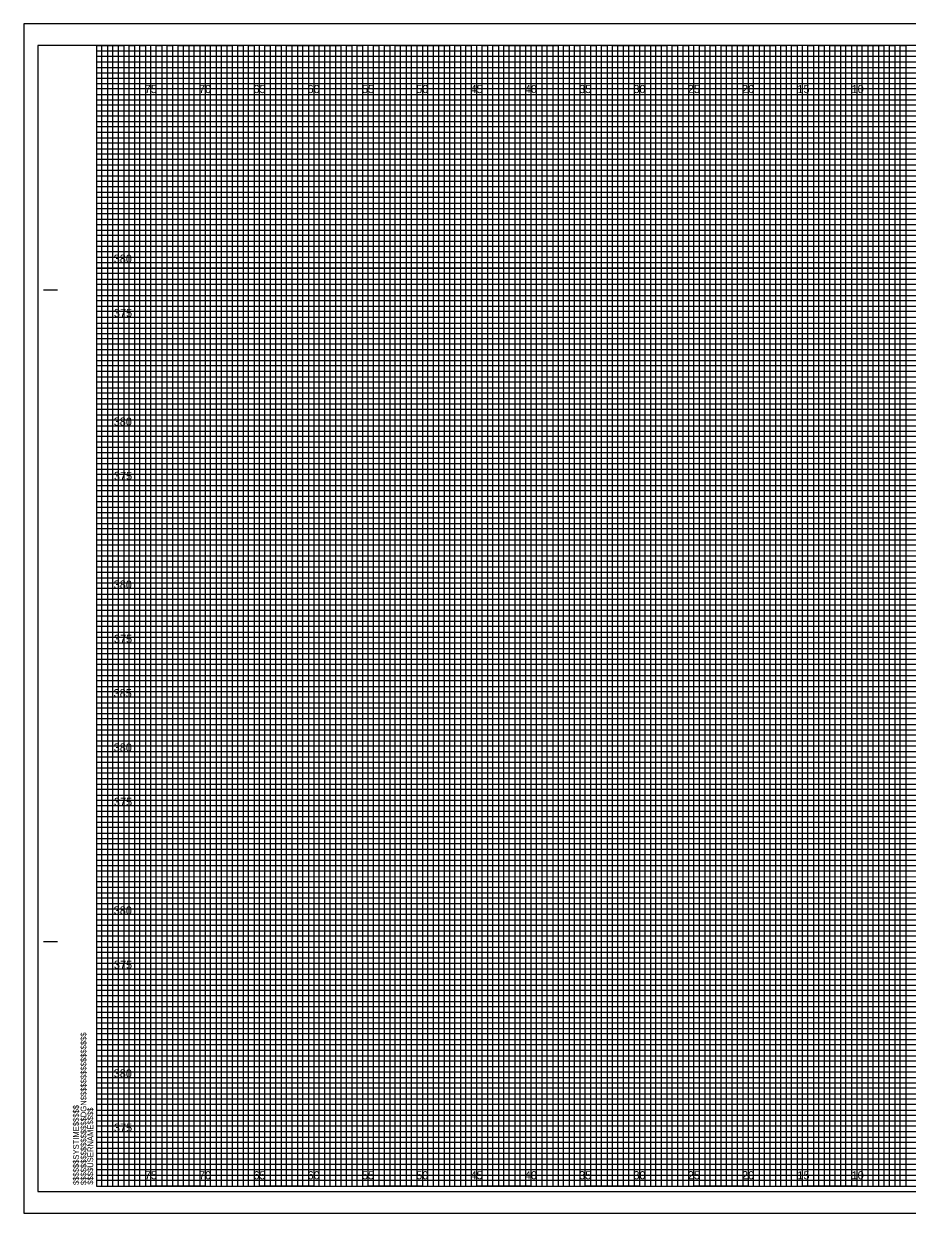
# Model space of a CAD drawing. Extents: x -7 to 162, y -2 to 217.
# Drawn here: x -6.7 to 74.6, y -2.5 to 107 of the extents above; entities that cross this region are included whole.
import ezdxf

# ---------------------------------------------------------------- set-up
doc = ezdxf.new("R2010")
doc.units = 0
for name, color, linetype in [('Exist Cross Section Cell', 7, 'Continuous'), ('Prop CMT Pvmt Course 1', 7, 'Continuous'), ('Prop CMT Pvmt Course 3', 7, 'Continuous'), ('Prop CMT Shld Paved Course 1', 7, 'Continuous'), ('Prop CMT Shld Paved Course 2', 7, 'Continuous'), ('Prop CMT Shld Paved Course 3', 7, 'Continuous'), ('Prop CMT Slope Grass', 7, 'Continuous'), ('Prop CMT Subgrade Earthwork', 7, 'Continuous'), ('Scratch_Level_3', 7, 'Continuous')]:
    doc.layers.add(name, color=color, linetype=linetype)

msp = doc.modelspace()

# ---------------------------------------------------------------- linework, layer by layer
at = {"layer": 'Prop CMT Pvmt Course 3'}
msp.add_lwpolyline([(-6.7, -2.5), (161.65, -2.5), (161.65, 107), (-6.7, 107)], close=True, dxfattribs=at)
at = {"layer": 'Prop CMT Shld Paved Course 1'}
for p, q in [((0, 104.5), (110.95, 104.5)), ((110.95, 103.99), (0, 103.99)), ((0, 103.99), (0, 103.5)), ((0, 103.5), (110.95, 103.5)), ((110.95, 102.95), (0, 102.95)), ((0, 102.95), (0, 102)), ((0, 102), (160, 102))]:
    msp.add_line(p, q, dxfattribs=at)
for points in [[(0, 101.5), (135, 101.5), (160, 101.5)], [(160, 101), (0, 101)], [(0, 100.5), (160, 100.5)], [(160, 99.5), (0, 99.5)], [(0, 99), (160, 99)], [(160, 98.5), (0, 98.49)], [(0, 98), (160, 98)], [(160, 97), (0, 97)], [(0, 96.5), (160, 96.5), (160, 96), (0, 96)], [(0, 95.5), (160, 95.5), (160, 94.5), (0, 94.5)], [(0, 94), (160, 94), (160, 93.5), (0, 93.5)], [(0, 93), (160, 93), (160, 92), (0, 92)], [(0, 91.5), (160, 91.5), (160, 91), (0, 91)], [(0, 90.5), (160, 90.5), (160, 89.5), (0, 89.5)], [(0, 89), (160, 89), (160, 88.5), (0, 88.5)], [(0, 88), (160, 88), (160, 86.97), (160, 86.5), (160, 86), (0, 86)], [(0, 87), (160, 87), (160, 86.5), (0, 86.5)], [(0, 85.5), (160, 85.5), (160, 84.5), (0, 84.51)], [(0, 84.51), (160, 84.5), (160, 84), (0, 84)], [(0, 83.5), (160, 83.5), (160, 83), (0, 83)], [(0, 82), (160, 82), (160, 81.5), (0, 81.5)], [(0, 81), (160, 81), (160, 80.5), (0, 80.5)], [(-0.04, 79.44), (160, 79.44), (160, 78.94), (-0.04, 78.94)], [(0, 78.5), (160, 78.5), (160, 78), (0, 78)], [(0, 77), (160, 77), (160, 76.5), (0, 76.5)], [(0, 76), (160, 76), (160, 75.5), (0, 75.5)], [(0, 74.5), (160, 74.5), (160, 74), (0, 74)], [(0, 73.5), (160, 73.5), (160, 73), (0, 73)], [(0, 72), (160, 72), (160, 71.5), (0, 71.5)], [(0, 71), (160, 71), (160, 70.5), (0, 70.5)], [(0, 69.5), (160, 69.5), (159.99, 68.99), (0, 69)], [(0, 68.5), (160, 68.5), (160, 68), (0, 68)], [(0, 67), (160, 67), (160, 66.5), (0, 66.5)], [(0, 66), (160, 66), (160, 65.5), (0, 65.5)], [(0, 64.5), (160, 64.5), (160, 64), (0, 64)], [(0, 63.5), (160, 63.5), (160, 63), (0, 63)], [(0, 62), (160, 62), (160, 61.5), (0, 61.5)], [(0, 61), (160, 61), (160, 60.5), (0, 60.5)], [(0, 59.5), (160, 59.5), (160, 59), (0, 59)], [(0, 58.5), (160.03, 58.45), (160, 58), (0, 58)], [(0, 57), (160, 57), (160, 56.5), (0, 56.5)], [(0, 56), (160, 56), (160, 55.5), (0, 55.5)], [(0, 54.5), (160, 54.5), (160, 54), (0, 54)], [(0, 53.5), (160, 53.5), (160, 53), (0, 53)], [(0, 52), (160, 52), (160, 51.5), (0, 51.5)], [(0, 51), (160, 51), (160, 50.5), (0, 50.5)], [(0, 49.5), (160, 49.5), (160, 49), (0, 49)], [(0, 48.5), (160, 48.5), (160, 48), (0, 48)], [(0, 47), (160, 47), (160, 46.5), (0, 46.5)], [(0, 46), (160, 46), (160, 45.5), (0, 45.5)], [(0, 44.5), (160, 44.5), (160, 44), (0, 44)], [(0, 43.5), (160, 43.5), (160, 43), (0, 43)], [(0, 42), (160, 42), (160, 41.5), (0, 41.5)], [(0, 41), (160, 41), (160, 40.5), (0, 40.5)], [(0, 39.5), (160, 39.5), (159.99, 38.99), (0, 39)], [(0, 38.5), (160, 38.5), (160, 38), (0, 38)], [(0, 37), (160, 37), (160, 36.5), (0, 36.5)], [(0, 36), (160, 36), (160, 35.5), (0, 35.5)], [(0, 34.5), (160, 34.5), (160, 34), (0, 34)], [(0, 33.5), (160, 33.5), (160, 33), (0, 33)], [(0, 32), (160, 32), (160, 31.5), (0, 31.5)], [(0, 31), (160, 31), (160, 30.5), (0, 30.5)], [(0, 29.5), (160, 29.5), (160, 29), (0, 29)], [(0, 28.5), (160.03, 28.46), (160, 28), (0, 28)], [(0, 27), (160, 27), (160, 26.5), (0, 26.5)], [(0, 26), (160, 26), (160, 25.5), (0, 25.5)], [(0, 24.5), (160, 24.5), (160, 24), (0, 24)], [(0, 23.5), (160, 23.5), (160, 23), (0, 23)], [(0, 22), (160, 22), (160, 21.5), (0, 21.5)], [(0, 21), (160, 21), (160, 20.5), (0, 20.5)], [(0, 19.5), (160, 19.5), (160, 19), (0, 19)], [(0, 18.5), (160, 18.5), (160, 18), (0, 18)], [(0, 17), (160, 17), (160, 16.5), (0, 16.5)], [(0, 16), (160, 16), (160, 15.5), (0, 15.5)], [(0, 14.5), (160, 14.5), (160, 14), (0, 14)], [(0, 13.5), (160, 13.5), (160, 13), (0, 13)], [(0, 12), (160, 12), (160, 11.5), (0, 11.5)], [(0, 11), (160, 11), (160, 10.5), (0, 10.5)], [(0, 9.5), (160, 9.5), (160, 9), (0, 9)], [(0, 8.5), (160, 8.5), (160, 8), (0, 8)], [(0, 7), (160, 7), (160, 6.5), (0, 6.5)], [(0, 6), (160, 6), (160, 5.5), (0, 5.5)], [(0, 4.5), (160, 4.5), (160, 4), (0, 4)], [(0, 3.5), (160, 3.5), (160, 3), (0, 3)], [(0, 2), (160, 2), (160, 1.5), (0, 1.5)], [(0, 1), (160, 1), (160, 0.5), (0, 0.5)]]:
    msp.add_lwpolyline(points, dxfattribs=at)
at = {"layer": 'Prop CMT Shld Paved Course 2'}
for p, q in [((-4.9, 82.5), (-3.65, 82.5)), ((-4.85, 82.5), (-3.6, 82.5)), ((-4.9, 22.5), (-3.65, 22.5)), ((-4.85, 22.5), (-3.6, 22.5)), ((0, 0), (0, 0)), ((0, 0), (0, 0)), ((0, 0), (0, 0)), ((0, 0), (0, 0)), ((0, 0), (0, 0)), ((0, 0), (0, 0)), ((0, 0), (0, 0))]:
    msp.add_line(p, q, dxfattribs=at)
msp.add_lwpolyline([(160, 105), (0, 105), (0, 0), (160, 0)], close=True, dxfattribs=at)
at = {"layer": 'Prop CMT Shld Paved Course 3'}
for points in [[(0, 0), (0.5, 0), (0.5, 105), (1, 105), (1, 0)], [(1, 0), (1.5, 0), (1.5, 105), (2, 105), (2, 0)], [(2.5, 0), (3, 0), (3, 105), (3.5, 105), (3.5, 0)], [(3.5, 0), (4, 0), (4, 105), (4.5, 105), (4.5, 0)], [(5, 0), (5.5, 0), (5.5, 105), (6, 105), (6, 0)], [(6, 0), (6.5, 0), (6.5, 105), (7, 105), (7, 0)], [(7.5, 0), (8, 0), (8, 105), (8.5, 105), (8.5, 0)], [(8.5, 0), (9, 0), (9, 105), (9.5, 105), (9.5, 0)], [(10, 0), (10.5, 0), (10.5, 105), (11, 105), (11, 0)], [(11, 0), (11.5, 0), (11.5, 105), (12, 105), (12, 0)], [(12.5, 0), (13, 0), (13, 105), (13.5, 105), (13.5, 0)], [(13.5, 0), (14, 0), (14, 105), (14.5, 105), (14.5, 0)], [(15, 0), (15.5, 0), (15.5, 105), (16, 105), (16, 0)], [(16, 0), (16.5, 0), (16.5, 105), (17, 105), (17, 0)], [(17.5, 0), (18, 0), (18, 105), (18.5, 105), (18.5, 0)], [(18.5, 0), (19, 0), (19, 105), (19.5, 105), (19.5, 0)], [(20, 0), (20.5, 0), (20.5, 105), (21, 105), (21, 0)], [(21, 0), (21.5, 0), (21.5, 105), (22, 105), (22, 0)], [(22.5, 0), (23, 0), (23, 105), (23.5, 105), (23.5, 0)], [(23.5, 0), (24, 0), (24, 105), (24.5, 105), (24.5, 0)], [(25, 0), (25.5, 0), (25.5, 105), (26, 105), (26, 0)], [(26, 0), (26.5, 0), (26.5, 105), (27, 105), (27, 0)], [(27.5, 0), (28, 0), (28, 105), (28.5, 105), (28.5, 0)], [(28.5, 0), (29, 0), (29, 105), (29.5, 105), (29.5, 0)], [(30, 0), (30.5, 0), (30.5, 105), (31, 105), (31, 0)], [(31, 0), (31.5, 0), (31.5, 105), (32, 105), (32, 0)], [(32.5, 0), (33, 0), (33, 105), (33.5, 105), (33.5, 0)], [(33.5, 0), (34, 0), (34, 105), (34.5, 105), (34.5, 0)], [(35, 0), (35.5, 0), (35.5, 105), (36, 105), (36, 0)], [(36, 0), (36.5, 0), (36.5, 105), (37, 105), (37, 0)], [(37.5, 0), (38, 0), (38, 105), (38.5, 105), (38.5, 0)], [(38.5, 0), (39, 0), (39, 105), (39.5, 105), (39.5, 0)], [(40, 0), (40.5, 0), (40.5, 105), (41, 105), (41, 0)], [(41, 0), (41.5, 0), (41.5, 105), (42, 105), (42, 0)], [(42.5, 0), (43, 0), (43, 105), (43.5, 105), (43.5, 0)], [(43.5, 0), (44, 0), (44, 105), (44.5, 105), (44.5, 0)], [(45, 0), (45.5, 0), (45.5, 105), (46, 105), (46, 0)], [(46, 0), (46.5, 0), (46.5, 105), (47, 105), (47, 0)], [(47.5, 0), (48, 0), (48, 105), (48.5, 105), (48.5, 0)], [(48.5, 0), (49, 0), (49, 105), (49.5, 105), (49.5, 0)], [(50, 0), (50.5, 0), (50.5, 105), (51, 105), (51, 0)], [(51, 0), (51.5, 0), (51.5, 105), (52, 105), (52, 0)], [(52.5, 0), (53, 0), (53, 105), (53.5, 105), (53.5, 0)], [(53.5, 0), (54, 0), (54, 105), (54.5, 105), (54.5, 0)], [(55, 0), (55.5, 0), (55.5, 105), (56, 105), (56, 0)], [(56, 0), (56.5, 0), (56.5, 105), (57, 105), (57, 0)], [(57.5, 0), (58, 0), (58, 105), (58.5, 105), (58.5, 0)], [(58.5, 0), (59, 0), (59, 105), (59.5, 105), (59.5, 0)], [(60, 0), (60.5, 0), (60.5, 105), (61, 105), (61, 0)], [(61, 0), (61.5, 0), (61.5, 105), (62, 105), (62, 0)], [(62.5, 0), (63, 0), (63, 105), (63.5, 105), (63.5, 0)], [(63.5, 0), (64, 0), (64, 105), (64.5, 105), (64.5, 0)], [(65, 0), (65.5, 0), (65.5, 105), (66, 105), (66, 0)], [(66, 0), (66.5, 0), (66.5, 105), (67, 105), (67, 0)], [(67.5, 0), (68, 0), (68, 105), (68.5, 105), (68.5, 0)], [(68.5, 0), (69, 0), (69, 105), (69.5, 105), (69.5, 0)], [(70, 0), (70.5, 0), (70.5, 105), (71, 105), (71, 0)], [(71, 0), (71.5, 0), (71.5, 105), (72, 105), (72, 0)], [(72.5, 0), (73, 0), (73, 105), (73.5, 105), (73.5, 0)], [(73.5, 0), (74, 0), (74, 105), (74.5, 105), (74.5, 0)]]:
    msp.add_lwpolyline(points, dxfattribs=at)
at = {"layer": 'Prop CMT Slope Grass'}
for points in [[(0, 105), (2.5, 105), (2.5, 0), (7.5, 0), (7.5, 105), (12.5, 105), (12.5, 0), (17.5, 0), (17.5, 105), (22.5, 105), (22.5, 0), (27.5, 0), (27.5, 105), (32.5, 105), (32.5, 0), (37.5, 0), (37.5, 105), (42.5, 105), (42.5, 0), (47.5, 0), (47.5, 105), (52.5, 105), (52.5, 0), (57.5, 0), (57.5, 105), (62.5, 105), (62.5, 0), (67.5, 0), (67.5, 105), (72.5, 105), (72.5, 0), (77.5, 0)], [(0, 102.5), (137.5, 102.5)], [(0, 92.5), (160, 92.5), (160, 102.5)], [(160, 97.5), (0, 97.5)], [(0, 82.5), (160, 82.5), (160, 87.5), (0, 87.5)], [(0, 72.5), (160, 72.5), (160, 77.5), (0, 77.5)], [(0, 62.5), (160, 62.5), (160, 67.5), (0, 67.5)], [(0, 52.5), (160, 52.5), (160, 57.5), (0, 57.5)], [(0, 42.5), (160, 42.5), (160, 47.5), (0, 47.5)], [(0, 32.5), (160, 32.5), (160, 37.5), (0, 37.5)], [(0, 22.5), (160, 22.5), (160, 27.5), (0, 27.5)], [(0, 12.5), (160, 12.5), (160, 17.5), (0, 17.5)], [(0, 2.5), (160, 2.5), (160, 7.5), (0, 7.5)]]:
    msp.add_lwpolyline(points, dxfattribs=at)
at = {"layer": 'Prop CMT Subgrade Earthwork'}
msp.add_lwpolyline([(-5.4, -0.5), (161.2, -0.5), (161.2, 105), (-5.4, 105)], close=True, dxfattribs=at)
at = {"layer": 'Scratch_Level_3'}
for p, q in [((5, 105), (0, 105)), ((5, 0), (5, 105)), ((15, 105), (10, 105)), ((10, 105), (10, 0)), ((15, 0), (15, 105)), ((25, 105), (20, 105)), ((20, 105), (20, 0)), ((25, 0), (25, 105)), ((35, 105), (30, 105)), ((30, 105), (30, 0)), ((35, 0), (35, 105)), ((45, 105), (40, 105)), ((40, 105), (40, 0)), ((45, 0), (45, 105)), ((55, 105), (50, 105)), ((50, 105), (50, 0)), ((55, 0), (55, 105)), ((65, 105), (60, 105)), ((60, 105), (60, 0)), ((65, 0), (65, 105)), ((75, 105), (70, 105)), ((70, 105), (70, 0)), ((10, 0), (5, 0)), ((20, 0), (15, 0)), ((30, 0), (25, 0)), ((40, 0), (35, 0)), ((60, 0), (55, 0)), ((70, 0), (65, 0)), ((50, 0), (45, 0))]:
    msp.add_line(p, q, dxfattribs=at)
for points in [[(160, 102.5), (160, 95), (0, 95)], [(0, 100), (160, 100)], [(0, 90), (160, 90), (160, 85), (0, 85)], [(0, 80), (160, 80), (160, 75), (0, 75)], [(0, 70), (160, 70), (160, 65), (0, 65)], [(0, 60), (160, 60), (160, 55), (0, 55)], [(0, 50), (160, 50), (160, 45), (0, 45)], [(0, 40), (160, 40), (160, 35), (0, 35)], [(0, 30), (160, 30), (160, 25), (0, 25)], [(0, 20), (160, 20), (160, 15), (0, 15)], [(0, 10), (160, 10), (160, 5), (0, 5)]]:
    msp.add_lwpolyline(points, dxfattribs=at)

# ---------------------------------------------------------------- texts
at = {"layer": 'Exist Cross Section Cell'}
for s, p in [('75', (4.44, 100.62)), ('70', (9.43, 100.62)), ('65', (14.44, 100.62)), ('60', (19.43, 100.62)), ('55', (24.44, 100.62)), ('50', (29.43, 100.62)), ('45', (34.44, 100.62)), ('40', (39.43, 100.62)), ('35', (44.44, 100.62)), ('30', (49.43, 100.62)), ('25', (54.44, 100.62)), ('20', (59.43, 100.62)), ('15', (64.53, 100.62)), ('10', (69.52, 100.62)), ('75', (4.44, 0.62)), ('70', (9.43, 0.62)), ('65', (14.44, 0.62)), ('60', (19.43, 0.62)), ('55', (24.44, 0.62)), ('50', (29.43, 0.62)), ('45', (34.44, 0.62)), ('40', (39.43, 0.62)), ('35', (44.44, 0.62)), ('30', (49.43, 0.62)), ('25', (54.44, 0.62)), ('20', (59.43, 0.62)), ('15', (64.53, 0.62)), ('10', (69.52, 0.62))]:
    msp.add_text(s, height=0.75, dxfattribs=at).set_placement(p)
at = {"layer": 'Prop CMT Pvmt Course 1'}
for s, p in [('380', (1.58, 85)), ('375', (1.6, 80)), ('380', (1.58, 70)), ('375', (1.6, 65)), ('380', (1.58, 55)), ('375', (1.6, 50)), ('385', (1.57, 45)), ('380', (1.58, 40)), ('375', (1.6, 35)), ('380', (1.58, 25)), ('375', (1.6, 20)), ('380', (1.58, 10)), ('375', (1.6, 5))]:
    msp.add_text(s, height=0.75, dxfattribs=at).set_placement(p)
at = {"layer": 'Prop CMT Shld Paved Course 2'}
for s, p in [('$$$$$$$$$$$$$$$$DGN$$$$$$$$$$$$$$$$', (-0.94, 0.09)), ('$$$$$$SYSTIME$$$$$', (-1.63, 0.09)), ('$$$$USERNAME$$$$', (-0.31, 0.12))]:
    msp.add_text(s, height=0.525, rotation=90, dxfattribs=at).set_placement(p)

doc.saveas('drawing.dxf')
